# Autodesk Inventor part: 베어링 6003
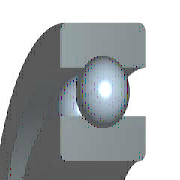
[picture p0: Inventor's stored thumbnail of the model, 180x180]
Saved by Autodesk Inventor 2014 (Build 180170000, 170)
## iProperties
Created: 2012-02
Part Number: 베어링 6003
Material: 강철, 연강
Description: 깊은 그루브 볼 베어링
Document SubType Name: Modeling
Standard: KS B 2023
Designer: mduedu
Standards Organization: KS
Language: ko-KR
Size Designation: 6003 - 17 x 35 x 10
Categories: <MemberInstance><Categories><Category DisplayName="샤프트 부품" InternalName="7f7aeb1f-a693-4053-b835-cee3144e0d98" Mnemonic="SHFT"><Category DisplayName="베어링" Inter
Density: 7.86 g/cm^3
Appearance: 노란색
Mass: 35.231 g
Surface Area: 48.7538 cm^2
Volume: 4.48231 cm^3
IsCustomPart: 1
Author: mduedu
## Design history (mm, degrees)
sketch "스케치" dims "d0" = 4.68 (= -0.26 x WD + 0.26 x BD)
  geometry: L1 (2.66, 13)-(7.34, 13); L2 (5, 13)-(5, 10.66); L3 (5, 13)-(5, 15.34); L4 (3.261, 11.434)-(0, 11.434); L5 (0, 8.5)-(10, 8.5); L6 (3.261, 14.566)-(0, 14.566); L7 (0, 17.5)-(10, 17.5); L8 (10, 8.5)-(10, 11.434); L9 (6.739, 11.434)-(10, 11.434); L10 (6.739, 14.566)-(10, 14.566); L11 (10, 17.5)-(10, 14.566); L12 (-1.4, 0)-(8.4, 0) reference; L13 (0, -0.3)-(0, 5.3) reference
  constraints: 22 end point, 4 point on line, 2 collinear, 2 perpendicular, 2 symmetric about line, 1 midpoint, 1 parallel, 14 other
  dimensions: "d9" = 17 diameter of L5 L12 (= WD); "d11" = 35 diameter of L7 L12 (= BD); "d12" = 10 distance between parallel lines of L8 L13 (= KB); "d13" = 22.868 diameter of L9 L12 (= 0.326 x BD + 0.674 x WD)
revolve "본체" stored, may be unused: angle "d6" = 90 deg
revolve "볼" stored, may be unused: angle "d7" = 90 deg
pattern_circular "IDS_ARRAYBALL[SIMPL:T]" dims angle "d3" = 360 deg
body "Solid1"
fillet "모깎기1" dims "d1" = 0.3 (= KRS)
other parameters: "WD" = 17 [user parameter; used in 5 equation terms], "BD" = 35 [user parameter; used in 5 equation terms], "KB" = 10 [user parameter; used in 1 equation term], "KRS" = 0.3 [user parameter; used in 1 equation term], "d4" = 0, "d5" = 0, "d8" = 0, "d14" = 0, "d15" = 0, "BBA" = 0 [user parameter], "BC0" = 3250000 [user parameter], "BC" = 6050000 [user parameter], "BR" = 17.5 (= 0.5 x BD) [user parameter], "WR" = 8.5 (= 0.5 x WD) [user parameter]
